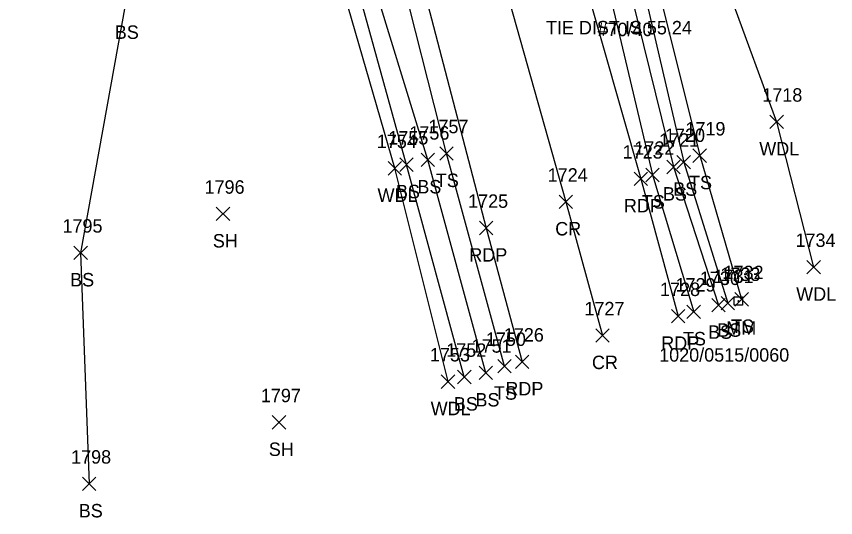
# Model space of a CAD drawing. Extents: x 1885914 to 1887218, y 756253 to 760620.
# Drawn here: x 1886409.9 to 1886531.6, y 759308 to 759382.5 of the extents above; entities that cross this region are included whole.
import ezdxf

# ---------------------------------------------------------------- set-up
doc = ezdxf.new("R2010")
doc.units = 0
for name, color, linetype in [('C_C', 7, 'Continuous'), ('L_A', 7, 'Continuous'), ('L_I', 7, 'Continuous'), ('L_TIC', 7, 'Continuous'), ('LAWA', 7, 'Continuous'), ('LELB', 7, 'Continuous'), ('P_A', 7, 'Continuous'), ('P_I', 7, 'Continuous'), ('P_TIC', 7, 'Continuous'), ('PET', 7, 'Continuous'), ('PRC', 7, 'Continuous'), ('S_A', 7, 'Continuous'), ('S_C', 7, 'Continuous'), ('S_I', 7, 'Continuous'), ('SRM', 7, 'Continuous'), ('U_C', 7, 'Continuous')]:
    doc.layers.add(name, color=color, linetype=linetype)

msp = doc.modelspace()

# ---------------------------------------------------------------- linework, layer by layer
at = {"layer": 'L_TIC'}
for points in [[(1886521.87, 759365.86), (1886523.87, 759367.86)], [(1886523.87, 759365.86), (1886521.87, 759367.86)], [(1886472.8, 759361.16), (1886474.8, 759363.16)], [(1886474.8, 759361.16), (1886472.8, 759363.16)], [(1886510.44, 759360.83), (1886512.44, 759362.83)], [(1886512.44, 759360.83), (1886510.44, 759362.83)], [(1886466.85, 759359.49), (1886468.85, 759361.49)], [(1886468.85, 759359.49), (1886466.85, 759361.49)], [(1886470.03, 759360.21), (1886472.03, 759362.21)], [(1886472.03, 759360.21), (1886470.03, 759362.21)], [(1886508.06, 759359.87), (1886510.06, 759361.87)], [(1886510.06, 759359.87), (1886508.06, 759361.87)], [(1886465.13, 759358.95), (1886467.13, 759360.95)], [(1886467.13, 759358.95), (1886465.13, 759360.95)], [(1886506.53, 759359.15), (1886508.53, 759361.15)], [(1886508.53, 759359.15), (1886506.53, 759361.15)], [(1886503.42, 759357.96), (1886505.42, 759359.96)], [(1886505.42, 759357.96), (1886503.42, 759359.96)], [(1886439.59, 759352.17), (1886441.59, 759354.17)], [(1886441.59, 759352.17), (1886439.59, 759354.17)], [(1886418.42, 759346.38), (1886420.42, 759348.38)], [(1886420.42, 759346.38), (1886418.42, 759348.38)], [(1886527.37, 759344.25), (1886529.37, 759346.25)], [(1886529.37, 759344.25), (1886527.37, 759346.25)], [(1886513.24, 759338.59), (1886515.24, 759340.59)], [(1886515.24, 759338.59), (1886513.24, 759340.59)], [(1886514.61, 759338.89), (1886516.61, 759340.89)], [(1886516.61, 759338.89), (1886514.61, 759340.89)], [(1886516.67, 759339.46), (1886518.67, 759341.46)], [(1886518.67, 759339.46), (1886516.67, 759341.46)], [(1886509.54, 759337.61), (1886511.54, 759339.61)], [(1886511.54, 759337.61), (1886509.54, 759339.61)], [(1886481.43, 759329.53), (1886483.43, 759331.53)], [(1886483.43, 759329.53), (1886481.43, 759331.53)], [(1886475.45, 759327.91), (1886477.45, 759329.91)], [(1886477.45, 759327.91), (1886475.45, 759329.91)], [(1886478.66, 759328.52), (1886480.66, 759330.52)], [(1886480.66, 759328.52), (1886478.66, 759330.52)], [(1886473.03, 759327.22), (1886475.03, 759329.22)], [(1886475.03, 759327.22), (1886473.03, 759329.22)], [(1886447.9, 759321.16), (1886449.9, 759323.16)], [(1886449.9, 759321.16), (1886447.9, 759323.16)], [(1886419.7, 759312.02), (1886421.7, 759314.02)], [(1886421.7, 759312.02), (1886419.7, 759314.02)]]:
    msp.add_lwpolyline(points, dxfattribs=at)
at = {"layer": 'LAWA'}
for points in [[(1886460.31, 759591.25), (1886468.58, 759565.01), (1886481.47, 759530.19), (1886487.24, 759503.98), (1886489.47, 759466.46), (1886499.36, 759440.4), (1886509.45, 759403.39), (1886522.87, 759366.86), (1886528.37, 759345.25)], [(1886474.03, 759328.22), (1886466.13, 759359.95), (1886457.59, 759389.45), (1886449.45, 759426.56), (1886442.01, 759457.6), (1886435.91, 759484.2), (1886428.83, 759514.65), (1886425.07, 759533.66), (1886420.25, 759558.57), (1886411.95, 759586.16)]]:
    msp.add_lwpolyline(points, dxfattribs=at)
at = {"layer": 'LELB'}
for points in [[(1886482.43, 759330.53), (1886473.8, 759362.16), (1886466.41, 759391.35), (1886456.38, 759428.48), (1886448.84, 759459.02), (1886441.76, 759486.12), (1886435.76, 759515.56), (1886431.42, 759535.05), (1886426.06, 759559.46), (1886421.11, 759588.4), (1886418.79, 759606.26), (1886412.24, 759623.91), (1886411.78, 759647.7), (1886414.35, 759668.8), (1886416.75, 759691.58), (1886420.37, 759713.7), (1886423.9, 759735.67), (1886428.12, 759754.98), (1886431.72, 759778.14), (1886436.25, 759795.18), (1886439.73, 759830.38)], [(1886479.66, 759329.52), (1886471.03, 759361.21), (1886461.96, 759390.83), (1886454.24, 759427.83), (1886447.27, 759458.84), (1886440.35, 759485.71), (1886434.88, 759515.3), (1886430.89, 759534.99), (1886424.93, 759559.47), (1886417.7, 759587.99), (1886415.39, 759606.58), (1886409.44, 759622.11), (1886408.97, 759647.11), (1886405.32, 759668.25), (1886398.3, 759701.89), (1886401.43, 759725.45)], [(1886476.45, 759328.91), (1886467.85, 759360.49), (1886459.66, 759390.14), (1886451.87, 759427.06), (1886445.59, 759458.5), (1886438.66, 759485.01), (1886433.8, 759515.01), (1886429.52, 759534.9), (1886422.3, 759559.11), (1886414.83, 759587.35), (1886411.02, 759591.73), (1886403.8, 759605.65), (1886400.43, 759619.74), (1886399.2, 759644.65), (1886399.26, 759666.38)], [(1886456.79, 759611.09), (1886455.06, 759603.13), (1886455.4, 759590.3), (1886459.57, 759560.59), (1886463.53, 759534.18), (1886472.77, 759498.14), (1886480.93, 759466.98), (1886488.08, 759436.33), (1886497.78, 759399.81), (1886507.53, 759360.15), (1886514.24, 759339.59)], [(1886475.5, 759468.65), (1886484.5, 759435), (1886494.85, 759399.45), (1886504.42, 759358.96), (1886510.54, 759338.61)], [(1886483.21, 759468.18), (1886491.35, 759437.83), (1886501.7, 759401.01), (1886511.44, 759361.83), (1886517.67, 759340.46)], [(1886437.16, 759462.49), (1886434.23, 759444.68), (1886432.6, 759421.79), (1886426.06, 759384.2), (1886419.42, 759347.38), (1886420.7, 759313.02)], [(1886488.08, 759436.33), (1886499.89, 759400.31), (1886509.06, 759360.87), (1886515.61, 759339.89)]]:
    msp.add_lwpolyline(points, dxfattribs=at)
at = {"layer": 'P_TIC'}
for points in [[(1886501.68, 759357.39), (1886503.68, 759359.39)], [(1886503.68, 759357.39), (1886501.68, 759359.39)], [(1886490.53, 759353.96), (1886492.53, 759355.96)], [(1886492.53, 759353.96), (1886490.53, 759355.96)], [(1886478.71, 759350.07), (1886480.71, 759352.07)], [(1886480.71, 759350.07), (1886478.71, 759352.07)], [(1886507.23, 759336.95), (1886509.23, 759338.95)], [(1886509.23, 759336.95), (1886507.23, 759338.95)], [(1886495.99, 759334.08), (1886497.99, 759336.08)], [(1886497.99, 759334.08), (1886495.99, 759336.08)], [(1886484.06, 759330.17), (1886486.06, 759332.17)], [(1886486.06, 759330.17), (1886484.06, 759332.17)]]:
    msp.add_lwpolyline(points, dxfattribs=at)
at = {"layer": 'PET'}
for points in [[(1886505.21, 759975.04), (1886485.32, 759931.76), (1886475.82, 759908.45), (1886466.13, 759882.96), (1886456.93, 759855.61), (1886449.99, 759833.06), (1886442.98, 759808.26), (1886435.87, 759778.49), (1886430.37, 759752.23), (1886424.92, 759721.57), (1886422.03, 759696.27), (1886420.3, 759670.71), (1886419.91, 759641.82), (1886421.23, 759616.47), (1886424.6, 759585.72), (1886430.09, 759554.32), (1886435.19, 759528.63), (1886443.72, 759490.84), (1886451.63, 759459.71), (1886459.13, 759429.12), (1886468.69, 759393.26), (1886479.71, 759351.07), (1886485.06, 759331.17)], [(1886526.14, 759964.92), (1886507.07, 759922.75), (1886498.17, 759900.86), (1886488.16, 759874.15), (1886479.62, 759848.04), (1886473, 759827.05), (1886466.37, 759803.11), (1886458.99, 759773.42), (1886453.36, 759746.97), (1886448.76, 759720.11), (1886445.71, 759693.61), (1886444.44, 759668.96), (1886443.78, 759643.55), (1886445.31, 759617.59), (1886448.26, 759589.04), (1886453.63, 759558.69), (1886458.27, 759533.55), (1886466.8, 759496), (1886474.35, 759464.49), (1886481.64, 759434.54), (1886491.18, 759398.8), (1886502.68, 759358.39), (1886508.23, 759337.95)]]:
    msp.add_lwpolyline(points, dxfattribs=at)
at = {"layer": 'PRC'}
msp.add_lwpolyline([(1886516.05, 759969.43), (1886496.99, 759926.69), (1886487.66, 759904.2), (1886477.68, 759877.96), (1886468.59, 759851.92), (1886461.77, 759829.93), (1886454.6, 759805.62), (1886447.16, 759775.82), (1886441.74, 759748.8), (1886436.89, 759720.56), (1886434.02, 759695.25), (1886432.32, 759669.09), (1886432.26, 759642.82), (1886433.77, 759616.6), (1886436.98, 759587.84), (1886441.74, 759556.93), (1886446.53, 759531.43), (1886454.86, 759493.34), (1886462.57, 759461.76), (1886470.69, 759431.8), (1886480.02, 759395.82), (1886491.53, 759354.96), (1886496.99, 759335.08)], dxfattribs=at)
at = {"layer": 'SRM'}
msp.add_lwpolyline([(1886516.57, 759340.82), (1886517.82, 759340.82), (1886517.82, 759339.57), (1886516.57, 759339.57)], close=True, dxfattribs=at)
msp.add_circle((1886517.2, 759340.19), 0.0833, dxfattribs=at)

# ---------------------------------------------------------------- texts
at = {"layer": 'C_C'}
msp.add_text('TIE DIST IS 55.24', height=2, dxfattribs=at).set_placement((1886488.58, 759379.87))
at = {"layer": 'L_A'}
for s, p in [('BS', (1886424.5, 759379.2)), ('WDL', (1886520.29, 759361.86)), ('TS', (1886472.21, 759357.16)), ('TS', (1886509.85, 759356.83)), ('BS', (1886469.47, 759356.21)), ('BS', (1886507.5, 759355.87)), ('WDL', (1886463.55, 759354.95)), ('BS', (1886466.29, 759355.49)), ('BS', (1886505.97, 759355.15)), ('TS', (1886502.83, 759353.96)), ('SH', (1886439.07, 759348.17)), ('BS', (1886417.86, 759342.38)), ('WDL', (1886525.78, 759340.25)), ('BS', (1886514.05, 759334.89)), ('TS', (1886516.08, 759335.46)), ('BS', (1886512.68, 759334.59)), ('TS', (1886508.95, 759333.61)), ('TS', (1886480.84, 759325.53)), ('BS', (1886474.89, 759323.91)), ('BS', (1886478.1, 759324.52)), ('WDL', (1886471.45, 759323.22)), ('SH', (1886447.39, 759317.16)), ('BS', (1886419.14, 759308.02))]:
    msp.add_text(s, height=2, dxfattribs=at).set_placement(p)
at = {"layer": 'L_I'}
for s, p in [('1718', (1886520.74, 759369.86)), ('1756', (1886468.28, 759364.21)), ('1757', (1886471.11, 759365.16)), ('1719', (1886509.31, 759364.83)), ('1754', (1886463.44, 759362.95)), ('1755', (1886465.15, 759363.49)), ('1721', (1886505.4, 759363.15)), ('1720', (1886506.28, 759363.87)), ('1722', (1886501.72, 759361.96)), ('1796', (1886437.84, 759356.17)), ('1795', (1886416.72, 759350.38)), ('1734', (1886525.67, 759348.25)), ('1732', (1886514.98, 759343.46)), ('1730', (1886511.46, 759342.59)), ('1731', (1886513.49, 759342.89)), ('1729', (1886507.84, 759341.61)), ('1751', (1886477.53, 759332.52)), ('1750', (1886479.65, 759333.53)), ('1753', (1886471.34, 759331.22)), ('1752', (1886473.76, 759331.91)), ('1797', (1886446.21, 759325.16)), ('1798', (1886418, 759316.02))]:
    msp.add_text(s, height=2, dxfattribs=at).set_placement(p)
at = {"layer": 'P_A'}
for s, p in [('RDP', (1886500.17, 759353.39)), ('CR', (1886489.96, 759349.96)), ('RDP', (1886477.19, 759346.07)), ('RDP', (1886505.72, 759332.95)), ('CR', (1886495.42, 759330.08)), ('RDP', (1886482.55, 759326.17))]:
    msp.add_text(s, height=2, dxfattribs=at).set_placement(p)
at = {"layer": 'P_I'}
for s, p in [('1723', (1886499.99, 759361.39)), ('1724', (1886488.84, 759357.96)), ('1725', (1886477.01, 759354.07)), ('1728', (1886505.54, 759340.95)), ('1727', (1886494.3, 759338.08)), ('1726', (1886482.32, 759334.17))]:
    msp.add_text(s, height=2, dxfattribs=at).set_placement(p)
at = {"layer": 'S_A'}
msp.add_text('MM', height=2, dxfattribs=at).set_placement((1886515.39, 759335.19))
at = {"layer": 'S_C'}
msp.add_text('1020/0515/0060', height=2, dxfattribs=at).set_placement((1886505.41, 759331.19))
at = {"layer": 'S_I'}
msp.add_text('1733', height=2, dxfattribs=at).set_placement((1886514.5, 759343.19))
at = {"layer": 'U_C'}
msp.add_text('#70/40', height=2, dxfattribs=at).set_placement((1886496.24, 759379.61))

doc.saveas('drawing.dxf')
